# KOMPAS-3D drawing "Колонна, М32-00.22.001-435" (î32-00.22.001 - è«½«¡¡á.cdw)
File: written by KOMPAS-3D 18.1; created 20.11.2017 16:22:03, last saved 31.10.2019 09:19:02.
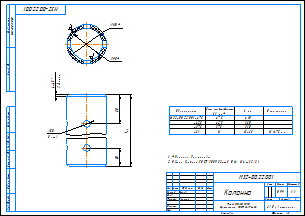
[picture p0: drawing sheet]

Sheet 1: A3, landscape

Document properties: Масса: 0.990487; Полное имя файла: М32-00.22.001 - Колонна.m3d

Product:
- Part/product: Колонна  | designation М32-00.22.001-435
    Масса: 1.21663
- Part/product: Колонна  | designation М32-00.22.001
    Масса: 1.0611
    Раздел спецификации: Детали
    Форматы листов документа: A3
    source file: М32-00.22.001 - Колонна.cdw
- Part/product: Колонна  | designation М32-00.22.001
    Масса: 0.990487
- Part/product: Колонна  | designation М40-10.22.001-ПВХ
    Масса: 0.677738
    source file: ..\Магна ins 40\Магна Ins 40-L-3-N-ПВХ\М40-10.22.001 - Колонна.cdw, М32-00.22.001 - Колонна.cdw

Title block, sheet 1: Наименование: Колонна; designation: М32-00.22.001; Масса: 0,99; scale: 1:1; Количество листов документа: 1; organisation: ЗАО «Астерион»; Форматы листов документа: A3; stored path: D:\Отработать\Магна 40\Чертежи\М40-00.22.001 - Колонна.cdw; Разработал: Милов; Т. контр.: Лучихин

Views: Вид 1, Местный разрез 1, Спереди, Проекционный вид 2
Referenced files in Z:\Магна\Магна Ins\Магна ins 32\: М32-00.22.001 - Колонна.m3d
Referenced files in D:\Отработать\Магна 40\3Д\: М40-00.22.001 - Колонна.m3d
Referenced files in D:\Magna\Магна Ins\Магна ins 32\: М32-00.22.001 - Колонна.m3d
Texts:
  Труба 110х10 PN10
  Полипропилен  ГОСТ 26996-86
  Длина погружной части
  L1, мм*
  L, мм
  L1 475 мм
Dimensions and other numbers on the sheet: 475; 410; -425; -375; 425; 375; 360; 310; 110; 90; 50; 80; 20; 8 отв.; 4; 2 фаски; 1:1; 1; 0,99

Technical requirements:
  * Размеры для справок.
  Общие допуски ГОСТ 30893.2-mK (H14, h14,  t2/2).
